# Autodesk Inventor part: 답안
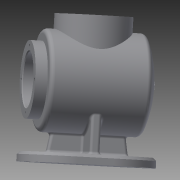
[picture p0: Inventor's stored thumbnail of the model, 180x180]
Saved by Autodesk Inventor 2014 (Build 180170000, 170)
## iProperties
Created: 2016-04
Part Number: 답안
Material: 일반
Document SubType Name: Modeling
Designer: owner
Density: 1 g/cm^3
Appearance: 기본값
Author: owner
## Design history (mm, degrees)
sketch "스케치1"
  geometry: C1 r 50 at (0, 0); 1 further point
  constraints: 1 centre point, 1 coincident
  dimensions: "d0" = 100 diameter of C1
extrude "돌출1" new body sketch "스케치1" distance "d1" = 110; taper "d2" = 0 deg
sketch "스케치2"
  geometry: C1 r 50 at (0, 0) reference; C2 r 38 at (0, 0)
  constraints: 1 centre point, 1 coincident
  dimensions: "d3" = 76 diameter of C2
extrude "돌출2" join sketch "스케치2" distance "d4" = 12; taper "d5" = 0 deg
sketch "스케치3"
  geometry: L1 (50, 110)-(-50, 110) reference; L2 (-50, 0)-(50, 0) reference; L3 (38, 122)-(-38, 122) reference; L4 (-38, 110)-(38, 110) reference; L5 (50, 0)-(50, 110) reference; L6 (50, 10.717)-(50, 0); A1 r 122 centre (0, 122) between (0, 0) and (50, 10.717); 2 further points
  constraints: 3 point on circle, 2 end point, 2 midpoint, 1 centre point, 1 collinear, 1 point on line, 1 vertical, 1 vertical alignment, 2 other
revolve "회전1" sketch "스케치3" stored, may be unused: angle "d6" = 90 deg
sketch "스케치4"
  geometry: L1 (50, 10.717)-(50, 110) reference; L2 (-50, 10.717)-(-50, 110) reference; L3 (50, 110)-(-50, 110) reference; L4 (47, 12.675)-(47, 107); L5 (47, 107)-(0, 107); L6 (0, 122)-(0, -8.698); A1 r 122 centre (0, 122) between (-50, 10.717) and (50, 10.717) reference; A2 r 119 centre (0, 122) between (0, 3) and (47, 12.675); 1 further point
  constraints: 6 end point, 2 point on circle, 2 point on line, 1 centre point
  dimensions: "d7" = 3 distance between parallel lines of L1 L4; "d8" = 3 radial gap between concentric circles of A1 A2
revolve "회전2" sketch "스케치4" stored, may be unused: angle "d9" = 90 deg
sketch "스케치5"
  geometry: C1 r 38 at (0, 0) reference; C2 r 27 at (0, 0)
  constraints: 1 centre point, 1 coincident
  dimensions: "d10" = 54 diameter of C2
extrude "돌출3" cut sketch "스케치5" distance "d11" = 25; taper "d12" = 0 deg
node "작업 평면2"
  node "작업 평면1"
sketch "스케치6"
  geometry: L1 (50, 10.717)-(-50, 10.717) reference; L2 (50, 110)-(-50, 110) reference; L3 (50, 10.717)-(50, 110) reference; C1 r 38 at (0, 60.358); 2 further points
  constraints: 1 centre point, 1 horizontal alignment, 1 midpoint, 1 vertical alignment
  dimensions: "d14" = 76 diameter of C1
extrude "돌출4" join sketch "스케치6" stored distance "d15" = 25; taper "d16" = 0 deg
sketch "스케치7"
  geometry: C1 r 38 at (0, 0) reference; C2 r 27 at (0, 0); 1 further point
  constraints: 1 centre point, 1 coincident
  dimensions: "d17" = 54 diameter of C2
extrude "돌출5" cut sketch "스케치7" distance "d18" = 25; taper "d19" = 0 deg
sketch "스케치8"
  geometry: L1 (-69, 127.858)-(-79, 127.858); L2 (-79, 127.858)-(-79, -7.142); L3 (-79, -7.142)-(-69, -7.142); L4 (-69, -7.142)-(-69, 127.858); L5 (-50, 10.717)-(-50, 110) reference; L6 (65, 98.358)-(65, 22.358) reference; L7 (50, 10.717)-(50, 110) reference; L8 (-69, 100.358)-(-50, 97.008); L9 (-69, 20.358)-(-48.684, 23.941); L10 (-50, 97.008)-(-48.684, 96.776); L11 (-48.684, 96.776)-(-48.684, 23.941); 3 further points
  constraints: 16 end point, 3 parallel, 3 point on line, 2 midpoint, 1 collinear, 1 horizontal, 1 horizontal alignment, 1 perpendicular
  dimensions: "d20" = 135 distance of L1.end L2.end; "d21" = 10 distance of L2.end L3.end; "d22" = 79 distance from line of L2 point (0, 0); "d23" = 40 distance of L8.start point (-69, 60.358); "d24" = 40 distance of L9.start point (-69, 60.358); "d25" = 100 deg angle of L4 L8; "d26" = 100 deg angle of L4 L9
extrude "돌출6" join sketch "스케치8" stored distance "d27" = 100; taper "d28" = 0 deg
extrude "돌출7" join sketch "스케치8" stored distance "d29" = 10; taper "d30" = 0 deg
node "작업 평면3"
sketch "스케치9"
  geometry: L1 (100, -10)-(0, -10) reference; L2 (0, 0)-(0, -10) reference; L3 (0, 0)-(100, 0) reference; L4 (100, -10)-(100, 0) reference; L5 (10, 0)-(10, 39); L6 (90, 0)-(90, 39); L7 (55, 0)-(55, 19.251) reference; L8 (45, 0)-(55, 0) reference; L9 (45, 19.251)-(45, 0) reference; A1 r 50 centre (50, 69) between (10, 39) and (90, 39) reference; A2 r 50 centre (50, 69) between (45, 19.251) and (55, 19.251) reference; 1 further point
  constraints: 4 end point, 3 parallel, 2 point on circle, 2 point on line
  dimensions: "d31" = 40 distance from line of point (50, 69) L5
  node "투영된 루프4"
  node "투영된 루프5"
feature "리브1" dims "d32" = 1, "d33" = 10, "d34" = 0, "d35" = 0, "d36" = 1, "d37" = 1
feature "리브2" dims "d38" = 1, "d39" = 10, "d40" = 0, "d41" = 0, "d42" = 1, "d43" = 1
sketch "스케치10"
  geometry: L1 (100, -135)-(100, 0) reference; L2 (0, -135)-(100, -135) reference; L3 (0, 0)-(0, -135) reference; L4 (0, 0)-(100, 0) reference; L5 (100, -67.5)-(0, -67.5); C1 r 5 at (50, -13.5); C2 r 5 at (50, -121.5); 1 further point
  constraints: 2 centre point, 2 end point, 2 midpoint
  dimensions: "d44" = 10 diameter of C1; "d45" = 10 diameter of C2; "d46" = 54 distance from line of L5 C1.centre; "d47" = 54 distance from line of L5 C2.centre
extrude "돌출8" cut sketch "스케치10" distance "d48" = 10; taper "d49" = 0 deg
fillet "모깎기1" dims "d50" = 50
sketch "스케치11"
  geometry: C1 r 27 at (0, 0) reference; 1 further point
  constraints: 1 vertical alignment
  dimensions: "d51" = 32.5 distance of C1.centre point (0, 32.5)
hole "구멍1" sketch "스케치11" at (0, 32.5) diameter "d52" = 3.242; stored, may be unused: countersink angle "d56" = 90 deg, drill point angle "d58" = 118 deg; dims "d53" = 8, "d54" = 4, "d55" = 2, "d57" = 10
sketch "스케치12"
  geometry: C1 r 38 at (0, 0) reference; 2 further points
  constraints: 1 vertical alignment
  dimensions: "d62" = 32.5 distance of C1.centre point (0, 32.5)
hole "구멍2" sketch "스케치12" at (0, 32.5) diameter "d63" = 3.242; stored, may be unused: countersink angle "d67" = 90 deg, drill point angle "d69" = 118 deg; dims "d64" = 8, "d65" = 4, "d66" = 2, "d68" = 10
node "작업 평면4"
sketch "스케치13"
  geometry: L1 (50, -79)-(-50, -79) reference; 2 further points
  constraints: 2 coincident, 1 other
feature "엠보싱1" sketch "스케치13" dims "d74" = 0.5, "d75" = 0
fillet "모깎기2" dims "d76" = 5
fillet "모깎기3" dims "d77" = 5
chamfer "모따기1" distance "d78" = 1; stored, may be unused: second distance "d79" = 2, angle "d80" = 45 deg
fillet "모깎기4" dims "d81" = 3
fillet "모깎기5" dims "d82" = 3
fillet "모깎기6" dims "d83" = 3
fillet "모깎기7" dims "d84" = 3
fillet "모깎기8" dims "d85" = 3
fillet "모깎기9" dims "d86" = 3
fillet "모깎기10" dims "d87" = 2
fillet "모깎기11" dims "d88" = 2
chamfer "모따기2" distance "d90" = 3; stored, may be unused: second distance "d91" = 2, angle "d92" = 45 deg
node "솔리드1"
pattern_circular "원형 패턴1" dims angle "d60" = 360 deg
pattern_circular "원형 패턴2" dims angle "d71" = 360 deg
node "투영된 루프1"
node "투영된 루프2"
node "투영된 루프3"
node "투영된 루프6"
other parameters: "d13" = 15
